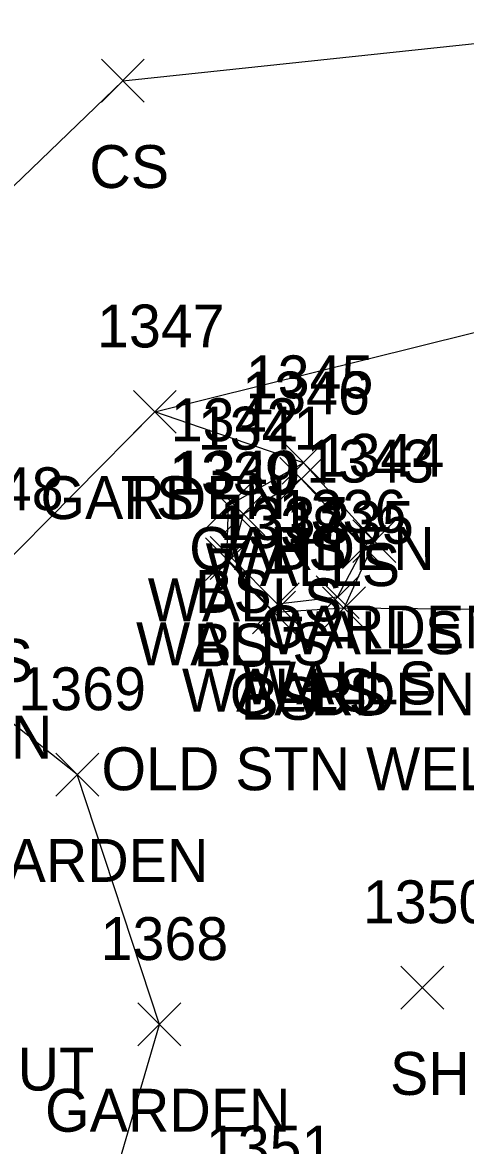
# Model space of a CAD drawing. Extents: x 1459992 to 1461532, y 647785 to 648535.
# Drawn here: x 1461405.5 to 1461426.2, y 648118.2 to 648170.5 of the extents above; entities that cross this region are included whole.
import ezdxf

# ---------------------------------------------------------------- set-up
doc = ezdxf.new("R2010")
doc.units = 0
for name, color, linetype in [('L_A', 7, 'Continuous'), ('L_C', 7, 'Continuous'), ('L_I', 7, 'Continuous'), ('L_TIC', 7, 'Continuous'), ('LAPB', 7, 'Continuous'), ('LELB', 7, 'Continuous'), ('LWS', 7, 'Continuous')]:
    doc.layers.add(name, color=color, linetype=linetype)

msp = doc.modelspace()

# ---------------------------------------------------------------- linework, layer by layer
at = {"layer": 'L_TIC'}
for points in [[(1461409.206, 648166.796), (1461411.206, 648168.796)], [(1461411.206, 648166.796), (1461409.206, 648168.796)], [(1461410.698, 648151.367), (1461412.698, 648153.367)], [(1461412.698, 648151.367), (1461410.698, 648153.367)], [(1461410.698, 648151.367), (1461412.698, 648153.367)], [(1461412.698, 648151.367), (1461410.698, 648153.367)], [(1461417.63, 648148.995), (1461419.63, 648150.995)], [(1461419.63, 648148.995), (1461417.63, 648150.995)], [(1461417.63, 648148.995), (1461419.63, 648150.995)], [(1461419.63, 648148.995), (1461417.63, 648150.995)], [(1461417.523, 648148.243), (1461419.523, 648150.243)], [(1461419.523, 648148.243), (1461417.523, 648150.243)], [(1461417.523, 648148.243), (1461419.523, 648150.243)], [(1461419.523, 648148.243), (1461417.523, 648150.243)], [(1461414.136, 648146.995), (1461416.136, 648148.995)], [(1461416.136, 648146.995), (1461414.136, 648148.995)], [(1461414.825, 648146.604), (1461416.825, 648148.604)], [(1461416.825, 648146.604), (1461414.825, 648148.604)], [(1461420.453, 648145.069), (1461422.453, 648147.069)], [(1461422.453, 648145.069), (1461420.453, 648147.069)], [(1461420.936, 648145.339), (1461422.936, 648147.339)], [(1461422.936, 648145.339), (1461420.936, 648147.339)], [(1461414.063, 648144.498), (1461416.063, 648146.498)], [(1461416.063, 648144.498), (1461414.063, 648146.498)], [(1461414.282, 648144.551), (1461416.282, 648146.551)], [(1461416.282, 648144.551), (1461414.282, 648146.551)], [(1461416.421, 648142.394), (1461418.421, 648144.394)], [(1461418.421, 648142.394), (1461416.421, 648144.394)], [(1461419.218, 648142.729), (1461421.218, 648144.729)], [(1461421.218, 648142.729), (1461419.218, 648144.729)], [(1461419.218, 648142.729), (1461421.218, 648144.729)], [(1461421.218, 648142.729), (1461419.218, 648144.729)], [(1461416.253, 648142.013), (1461418.253, 648144.013)], [(1461418.253, 648142.013), (1461416.253, 648144.013)], [(1461419.517, 648142.215), (1461421.517, 648144.215)], [(1461421.517, 648142.215), (1461419.517, 648144.215)], [(1461419.517, 648142.215), (1461421.517, 648144.215)], [(1461421.517, 648142.215), (1461419.517, 648144.215)], [(1461407.084, 648134.457), (1461409.084, 648136.457)], [(1461409.084, 648134.457), (1461407.084, 648136.457)], [(1461423.173, 648124.53), (1461425.173, 648126.53)], [(1461425.173, 648124.53), (1461423.173, 648126.53)], [(1461410.912, 648122.815), (1461412.912, 648124.815)], [(1461412.912, 648122.815), (1461410.912, 648124.815)]]:
    msp.add_lwpolyline(points, dxfattribs=at)
at = {"layer": 'LAPB'}
for points in [[(1461448.413, 648159.74), (1461440.459, 648145.814), (1461441.027, 648143.03), (1461420.517, 648143.215), (1461421.936, 648146.339), (1461418.63, 648149.995), (1461411.698, 648152.367), (1461431.401, 648157.265)], [(1461407.924, 648110.162), (1461411.912, 648123.815), (1461408.084, 648135.457), (1461400.813, 648141.208), (1461397.294, 648138.804), (1461398.931, 648128.614)]]:
    msp.add_lwpolyline(points, dxfattribs=at)
at = {"layer": 'LELB'}
for points in [[(1461400, 648157.981), (1461410.206, 648167.796), (1461433.497, 648170.261), (1461450.015, 648174.465), (1461460.23, 648178.212), (1461481.957, 648192.378), (1461506.16, 648200.217)], [(1461411.698, 648152.367), (1461404.189, 648144.779), (1461400.813, 648141.208)], [(1461420.517, 648143.215), (1461417.253, 648143.013), (1461415.063, 648145.498), (1461415.136, 648147.995), (1461418.63, 648149.995)]]:
    msp.add_lwpolyline(points, dxfattribs=at)
at = {"layer": 'LWS'}
for points in [[(1461420.218, 648143.729), (1461417.421, 648143.394), (1461415.282, 648145.551), (1461415.825, 648147.604), (1461418.523, 648149.243)], [(1461420.218, 648143.729), (1461421.453, 648146.069), (1461418.523, 648149.243)]]:
    msp.add_lwpolyline(points, dxfattribs=at)

# ---------------------------------------------------------------- texts
at = {"layer": 'L_A'}
for s, p in [('CS', (1461408.647, 648162.796)), ('GARDEN', (1461406.367, 648147.367)), ('TS', (1461410.107, 648147.367)), ('GARDEN', (1461413.299, 648144.995)), ('BS', (1461417.071, 648144.995)), ('WALLS', (1461414.066, 648144.243)), ('WALLS', (1461414.066, 648144.243)), ('BS', (1461413.577, 648142.995)), ('WALLS', (1461411.369, 648142.604)), ('GARDEN', (1461416.605, 648141.339)), ('WALLS', (1461416.996, 648141.069)), ('WALLS', (1461410.825, 648140.551)), ('BS', (1461413.504, 648140.498)), ('TS', (1461402.599, 648139.779)), ('WALLS', (1461415.762, 648138.729)), ('WALLS', (1461415.762, 648138.729)), ('WALLS', (1461412.964, 648138.394)), ('GARDEN', (1461415.186, 648138.215)), ('BS', (1461418.958, 648138.215)), ('BS', (1461415.694, 648138.013)), ('GARDEN', (1461395.483, 648136.208)), ('GARDEN', (1461402.754, 648130.457)), ('SH', (1461422.661, 648120.53)), ('GARDEN', (1461406.581, 648118.815))]:
    msp.add_text(s, height=2, dxfattribs=at).set_placement(p)
at = {"layer": 'L_C'}
for s, p in [('OLD STN WELL', (1461409.21, 648134.729)), ('OLD STN WELL', (1461409.21, 648134.729)), ('2M.AMERICAN WALNUT', (1461378.261, 648120.733))]:
    msp.add_text(s, height=2, dxfattribs=at).set_placement(p)
at = {"layer": 'L_I'}
for s, p in [('1347', (1461409.005, 648155.367)), ('1347', (1461409.005, 648155.367)), ('1345', (1461415.937, 648152.995)), ('1345', (1461415.937, 648152.995)), ('1346', (1461415.775, 648152.243)), ('1346', (1461415.775, 648152.243)), ('1342', (1461412.443, 648150.995)), ('1341', (1461413.699, 648150.604)), ('1344', (1461419.243, 648149.339)), ('1343', (1461418.76, 648149.069)), ('1339', (1461412.362, 648148.498)), ('1340', (1461412.502, 648148.551)), ('1348', (1461401.496, 648147.779)), ('1336', (1461417.47, 648146.729)), ('1336', (1461417.47, 648146.729)), ('1337', (1461414.728, 648146.394)), ('1335', (1461417.824, 648146.215)), ('1335', (1461417.824, 648146.215)), ('1338', (1461414.56, 648146.013)), ('1369', (1461405.336, 648138.457)), ('1350', (1461421.393, 648128.53)), ('1368', (1461409.172, 648126.815)), ('1351', (1461414.075, 648117.095))]:
    msp.add_text(s, height=2, dxfattribs=at).set_placement(p)

doc.saveas('drawing.dxf')
